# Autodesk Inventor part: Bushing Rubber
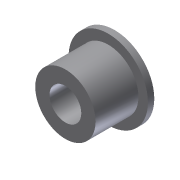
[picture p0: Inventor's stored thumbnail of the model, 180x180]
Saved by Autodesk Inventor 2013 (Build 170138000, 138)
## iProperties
Created: 2010-03
Part Number: Bushing Rubber
Document SubType Name: Modeling
Designer: bhakira
Density: 1 g/cm^3
Material: Generic
Author: bhakira
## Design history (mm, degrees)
sketch "Sketch1"
  geometry: L1 (25, 31)-(25, 27); L2 (25, 27)-(19, 27); L3 (19, 27)-(19, 0); L4 (19, 0)-(0, 0); L5 (0, 0)-(0, 31); L6 (0, 31)-(25, 31); 1 further point
  constraints: 12 end point, 1 coincident, 1 other
  dimensions: "d1" = 50 diameter of L1 L5; "d2" = 38 diameter of L3 L5; "d3" = 4 distance of L1.start L1.end; "d4" = 27 distance between parallel lines of L4 L2
revolve "Revolution1" sketch "Sketch1" stored, may be unused: angle "d5" = 90 deg
hole "Hole1" diameter "d8" = 20; stored, may be unused: countersink angle "d12" = 82 deg, drill point angle "d14" = 118 deg; dims "d6" = 10, "d7" = 10, "d9" = 6, "d10" = 34.925, "d11" = 2, "d13" = 8
body "Solid1"
